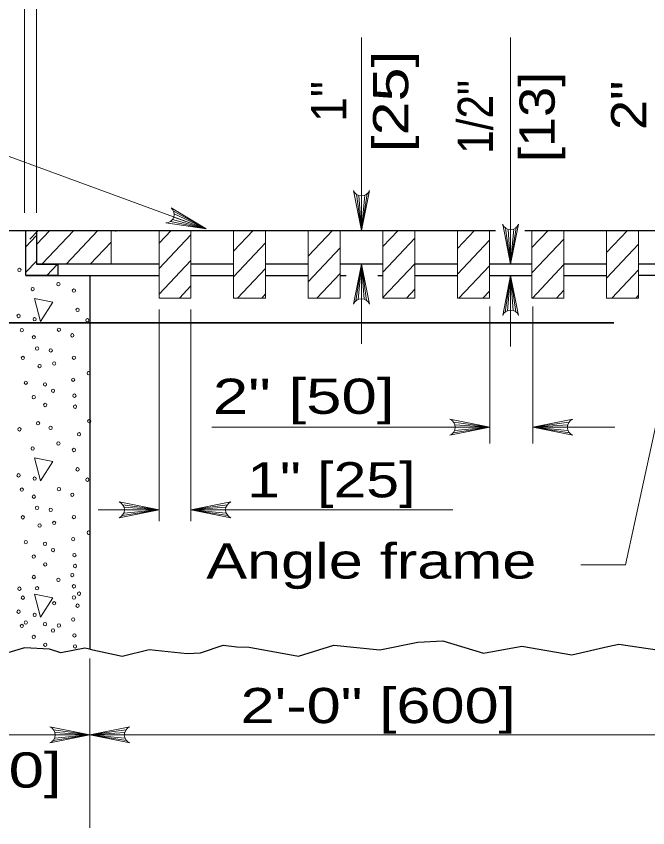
# Model space of a CAD drawing. Extents: x -410.5 to -376.5, y 1617.6 to 1661.6.
# Drawn here: x -394.159 to -391.362, y 1656.08 to 1659.678 of the extents above; entities that cross this region are included whole.
import ezdxf
from ezdxf.enums import TextEntityAlignment as Align

# ---------------------------------------------------------------- set-up
doc = ezdxf.new("R2010")
doc.units = 0
doc.header["$LTSCALE"] = 0.062
doc.layers.add('1', color=7, linetype='Continuous', lineweight=13)

msp = doc.modelspace()

# ---------------------------------------------------------------- linework, layer by layer
at = {"layer": '1'}
for p, q in [((-394.12283, 1658.80683), (-394.12283, 1659.937)), ((-394.06925, 1658.80683), (-394.06925, 1659.937)), ((-392.62967, 1658.72817), (-392.62967, 1659.58383)), ((-391.96883, 1658.57825), (-391.96883, 1659.58383)), ((-392.65208, 1658.88833), (-392.62967, 1658.72817)), ((-392.641, 1658.88292), (-392.62967, 1658.72817)), ((-392.60492, 1658.89025), (-392.62967, 1658.72817)), ((-392.61525, 1658.88417), (-392.62967, 1658.72817)), ((-392.62967, 1658.88133), (-392.62967, 1658.72817)), ((-393.46167, 1658.8135), (-393.31725, 1658.73575)), ((-393.46692, 1658.777), (-393.31725, 1658.73575)), ((-393.46158, 1658.78708), (-393.31725, 1658.73575)), ((-393.45942, 1658.80167), (-393.31725, 1658.73575)), ((-393.47575, 1658.76842), (-393.31725, 1658.73575)), ((-391.99125, 1658.7385), (-391.96883, 1658.57825)), ((-391.94408, 1658.74033), (-391.96883, 1658.57825)), ((-394.1165, 1658.65567), (-394.06933, 1658.70567)), ((-394.09842, 1658.68967), (-394.062, 1658.72817)), ((-394.06925, 1658.72817), (-394.06925, 1658.57825)), ((-394.06925, 1658.66575), (-394.01042, 1658.72808)), ((-394.04508, 1658.57833), (-393.90358, 1658.72808)), ((-393.93833, 1658.57833), (-393.79683, 1658.72808)), ((-393.73883, 1658.57825), (-393.73883, 1658.72817)), ((-393.71933, 1658.72375), (-393.71508, 1658.72817)), ((-393.5265, 1658.67183), (-393.47325, 1658.72817)), ((-393.5265, 1658.55875), (-393.38483, 1658.70867)), ((-393.34308, 1658.72817), (-393.48467, 1658.72817)), ((-393.19608, 1658.636), (-393.10908, 1658.72817)), ((-392.86567, 1658.61358), (-392.75758, 1658.72817)), ((-392.86567, 1658.72675), (-392.86433, 1658.72817)), ((-392.53533, 1658.65642), (-392.46758, 1658.72817)), ((-392.20483, 1658.64767), (-392.12883, 1658.72817)), ((-391.98017, 1658.733), (-391.96883, 1658.57825)), ((-391.9545, 1658.73425), (-391.96883, 1658.57825)), ((-391.96883, 1658.73142), (-391.96883, 1658.57825)), ((-391.8745, 1658.65258), (-391.80317, 1658.72817)), ((-391.54408, 1658.63008), (-391.45158, 1658.72817)), ((-393.8315, 1658.57833), (-393.73883, 1658.67642)), ((-393.19608, 1658.52292), (-393.0545, 1658.67283)), ((-392.53525, 1658.54342), (-392.39367, 1658.69333)), ((-392.20483, 1658.53458), (-392.06325, 1658.6845)), ((-391.8745, 1658.5395), (-391.73283, 1658.6895)), ((-391.54408, 1658.517), (-391.4025, 1658.667)), ((-392.86567, 1658.5005), (-392.72408, 1658.6505)), ((-394.1165, 1658.54267), (-394.06925, 1658.59258)), ((-393.5265, 1658.44567), (-393.38483, 1658.59558)), ((-394.02325, 1658.52825), (-393.97608, 1658.57825)), ((-393.17858, 1658.42833), (-393.0545, 1658.55983)), ((-392.65442, 1658.41608), (-392.62967, 1658.57825)), ((-392.64408, 1658.42225), (-392.62967, 1658.57825)), ((-392.62967, 1658.42508), (-392.62967, 1658.57825)), ((-392.61833, 1658.42342), (-392.62967, 1658.57825)), ((-392.60725, 1658.418), (-392.62967, 1658.57825)), ((-392.62967, 1658.57825), (-392.62967, 1658.22608)), ((-392.53525, 1658.43033), (-392.39367, 1658.58033)), ((-392.19842, 1658.42833), (-392.06325, 1658.5715)), ((-391.87275, 1658.42833), (-391.73283, 1658.57642)), ((-392.827, 1658.42833), (-392.72408, 1658.53742)), ((-391.99367, 1658.36608), (-391.96883, 1658.52825)), ((-391.98325, 1658.37225), (-391.96883, 1658.52825)), ((-391.96883, 1658.52825), (-391.96883, 1658.21383)), ((-391.96883, 1658.37508), (-391.96883, 1658.52825)), ((-391.9575, 1658.37342), (-391.96883, 1658.52825)), ((-391.94642, 1658.368), (-391.96883, 1658.52825)), ((-391.521, 1658.42833), (-391.4025, 1658.55392)), ((-393.436, 1658.42833), (-393.38483, 1658.4825)), ((-392.43042, 1658.42833), (-392.39367, 1658.46717)), ((-392.09158, 1658.42842), (-392.06325, 1658.45833)), ((-391.76592, 1658.42833), (-391.73283, 1658.46325)), ((-393.07175, 1658.42833), (-393.0545, 1658.44667)), ((-391.41425, 1658.42833), (-391.4025, 1658.44083)), ((-393.5265, 1658.37833), (-393.5265, 1657.43925)), ((-393.38483, 1658.37833), (-393.38483, 1657.43925)), ((-392.06133, 1658.39092), (-392.06133, 1657.78325)), ((-391.871, 1658.39092), (-391.871, 1657.78325)), ((-392.22158, 1657.87775), (-392.06133, 1657.85533)), ((-391.71075, 1657.87775), (-391.871, 1657.85533)), ((-393.29325, 1657.85533), (-392.0665, 1657.85533)), ((-392.2235, 1657.8305), (-392.06133, 1657.85533)), ((-392.21733, 1657.84092), (-392.06133, 1657.85533)), ((-392.21617, 1657.86658), (-392.06133, 1657.85533)), ((-392.2145, 1657.85533), (-392.06133, 1657.85533)), ((-391.71617, 1657.86658), (-391.871, 1657.85533)), ((-391.71783, 1657.85533), (-391.871, 1657.85533)), ((-391.715, 1657.84092), (-391.871, 1657.85533)), ((-391.70892, 1657.8305), (-391.871, 1657.85533)), ((-391.871, 1657.85533), (-391.50767, 1657.85533)), ((-393.79667, 1657.48925), (-393.5265, 1657.48925)), ((-393.68858, 1657.4645), (-393.5265, 1657.48925)), ((-393.68667, 1657.51167), (-393.5265, 1657.48925)), ((-393.6825, 1657.47483), (-393.5265, 1657.48925)), ((-393.68125, 1657.50058), (-393.5265, 1657.48925)), ((-393.67967, 1657.48925), (-393.5265, 1657.48925)), ((-393.22458, 1657.51167), (-393.38483, 1657.48925)), ((-393.23008, 1657.50058), (-393.38483, 1657.48925)), ((-393.23167, 1657.48925), (-393.38483, 1657.48925)), ((-393.22883, 1657.47483), (-393.38483, 1657.48925)), ((-393.22275, 1657.4645), (-393.38483, 1657.48925)), ((-393.38483, 1657.48925), (-392.22533, 1657.48925)), ((-393.83325, 1656.07967), (-393.83325, 1656.82983)), ((-393.9935, 1656.51367), (-393.83325, 1656.49125)), ((-393.673, 1656.51367), (-393.83325, 1656.49125)), ((-393.99542, 1656.4665), (-393.83325, 1656.49125)), ((-393.98925, 1656.47683), (-393.83325, 1656.49125)), ((-393.98808, 1656.50258), (-393.83325, 1656.49125)), ((-393.98642, 1656.49125), (-393.83325, 1656.49125)), ((-393.84033, 1656.49125), (-392.11067, 1656.49125)), ((-393.6785, 1656.50258), (-393.83325, 1656.49125)), ((-393.68008, 1656.49125), (-393.83325, 1656.49125)), ((-393.67725, 1656.47683), (-393.83325, 1656.49125)), ((-393.67117, 1656.4665), (-393.83325, 1656.49125)), ((-392.1675, 1656.49125), (-391.09567, 1656.49125))]:
    msp.add_line(p, q, dxfattribs=at)
at = {"layer": '1', "lineweight": 25}
for p, q in [((-394.14417, 1658.72817), (-394.09692, 1658.72817)), ((-394.1165, 1658.72817), (-392.03583, 1658.72817)), ((-391.90558, 1658.72817), (-390.8125, 1658.72817)), ((-393.527, 1658.57825), (-394.06925, 1658.57825)), ((-393.19542, 1658.57825), (-393.38483, 1658.57825)), ((-392.86633, 1658.57825), (-393.0545, 1658.57825)), ((-392.53475, 1658.57825), (-392.72408, 1658.57825)), ((-392.20567, 1658.57825), (-392.39483, 1658.57825)), ((-391.8745, 1658.57825), (-392.06325, 1658.57825)), ((-391.54408, 1658.57825), (-391.73283, 1658.57825)), ((-390.85967, 1658.57825), (-391.4025, 1658.57825)), ((-394.1165, 1658.52825), (-393.5265, 1658.52825)), ((-393.83325, 1658.52825), (-393.83325, 1656.87183)), ((-393.38483, 1658.52825), (-393.19608, 1658.52825)), ((-393.0545, 1658.52825), (-392.86567, 1658.52825)), ((-392.72408, 1658.52825), (-392.69817, 1658.52825)), ((-392.55742, 1658.52825), (-392.53642, 1658.52825)), ((-392.39483, 1658.52825), (-392.20483, 1658.52825)), ((-392.06325, 1658.52825), (-391.8745, 1658.52825)), ((-391.73283, 1658.52825), (-391.54408, 1658.52825)), ((-390.8125, 1658.52825), (-391.4025, 1658.52825))]:
    msp.add_line(p, q, dxfattribs=at)
at = {"layer": '1', "lineweight": 35}
for p, q in [((-395.32633, 1658.31867), (-393.57875, 1658.31867)), ((-393.57875, 1658.31867), (-391.51225, 1658.31867))]:
    msp.add_line(p, q, dxfattribs=at)
at = {"layer": '1'}
for points in [[(-393.31725, 1658.73575), (-394.90375, 1659.31708), (-395.14233, 1659.31708)], [(-392.59425, 1658.90517), (-392.62967, 1658.72817), (-392.66508, 1658.90517)], [(-393.47217, 1658.8285), (-393.31725, 1658.73575), (-393.49592, 1658.76175)], [(-391.9335, 1658.75525), (-391.96883, 1658.57825), (-392.00425, 1658.75525)], [(-393.19608, 1658.72817), (-393.19608, 1658.42833), (-393.0545, 1658.42833), (-393.0545, 1658.72817)], [(-392.66508, 1658.40125), (-392.62967, 1658.57825), (-392.59425, 1658.40125)], [(-392.00425, 1658.35125), (-391.96883, 1658.52825), (-391.9335, 1658.35125)], [(-391.18092, 1658.52825), (-391.4595, 1657.24567), (-391.65833, 1657.24567)], [(-392.23833, 1657.81992), (-392.06133, 1657.85533), (-392.23833, 1657.89067)], [(-391.694, 1657.81992), (-391.871, 1657.85533), (-391.694, 1657.89067)], [(-393.7035, 1657.45383), (-393.5265, 1657.48925), (-393.7035, 1657.52467)], [(-393.20783, 1657.45383), (-393.38483, 1657.48925), (-393.20783, 1657.52467)], [(-394.01025, 1656.45583), (-393.83325, 1656.49125), (-394.01025, 1656.52667)], [(-393.65625, 1656.45583), (-393.83325, 1656.49125), (-393.65625, 1656.52667)], [(-394.77725, 1656.49125), (-394.08308, 1656.49125), (-393.84033, 1656.49125)]]:
    msp.add_lwpolyline(points, dxfattribs=at)
at = {"layer": '1', "lineweight": 25}
for points in [[(-393.83325, 1656.87183), (-393.85467, 1656.87667), (-393.96075, 1656.85467), (-394.011, 1656.871), (-394.12183, 1656.87733), (-394.27542, 1656.83125), (-394.38142, 1656.86892), (-394.53508, 1656.83192), (-394.6515, 1656.87167), (-394.77725, 1656.87975), (-394.77725, 1658.5975), (-394.60742, 1658.72817), (-394.1165, 1658.72817)], [(-394.19133, 1658.72817), (-394.09692, 1658.72817), (-393.71933, 1658.72817)], [(-393.83325, 1656.87183), (-393.68983, 1656.83983), (-393.57033, 1656.87083), (-393.40175, 1656.85217), (-393.34308, 1656.855), (-393.2425, 1656.88925), (-393.18192, 1656.882), (-393.12783, 1656.87983), (-392.90825, 1656.84083), (-392.75167, 1656.88892), (-392.54808, 1656.86817), (-392.37933, 1656.90217), (-392.26933, 1656.909), (-392.08858, 1656.85375), (-391.91983, 1656.88475), (-391.69733, 1656.84675), (-391.53892, 1656.88275), (-391.48967, 1656.89375), (-391.23017, 1656.85558), (-391.09567, 1656.88817)]]:
    msp.add_lwpolyline(points, dxfattribs=at)
msp.add_lwpolyline([(-394.1165, 1658.52825), (-394.1165, 1658.72817), (-394.06925, 1658.72817), (-394.06925, 1658.57825), (-393.97483, 1658.57825), (-393.97483, 1658.52825)], close=True, dxfattribs=at)
at = {"layer": '1'}
for points in [[(-393.5265, 1658.72817), (-393.5265, 1658.42833), (-393.38483, 1658.42833), (-393.38483, 1658.72817)], [(-392.86567, 1658.72817), (-392.86567, 1658.42833), (-392.72408, 1658.42833), (-392.72408, 1658.72817)], [(-392.53525, 1658.72817), (-392.53525, 1658.42833), (-392.39367, 1658.42833), (-392.39367, 1658.72817)], [(-392.20483, 1658.72817), (-392.20483, 1658.42833), (-392.06325, 1658.42833), (-392.06325, 1658.72817)], [(-391.8745, 1658.72817), (-391.8745, 1658.42833), (-391.73283, 1658.42833), (-391.73283, 1658.72817)], [(-391.54408, 1658.72817), (-391.54408, 1658.42833), (-391.4025, 1658.42833), (-391.4025, 1658.72817)], [(-394.07833, 1658.42658), (-394.05133, 1658.32417), (-393.99633, 1658.41067)], [(-394.07833, 1657.71992), (-394.05133, 1657.61742), (-393.99633, 1657.70392)], [(-394.07833, 1657.11542), (-394.05133, 1657.01292), (-393.99633, 1657.09942)]]:
    msp.add_lwpolyline(points, close=True, dxfattribs=at)
for centre, start, end in [((-392.62971, 1658.91942), 202.08782, 337.91395), ((-393.49749, 1658.79989), 272.47392, 48.30005), ((-391.9689, 1658.76951), 202.08782, 337.91395), ((-392.62963, 1658.38692), 22.08782, 157.91395), ((-391.96882, 1658.33695), 22.08782, 157.91395), ((-392.25263, 1657.85533), 292.08605, 67.91218), ((-391.67972, 1657.85533), 112.08782, 247.91395), ((-393.71776, 1657.4893), 292.08605, 67.91218), ((-393.19357, 1657.4893), 112.08782, 247.91395), ((-394.02458, 1656.49131), 292.08605, 67.91218), ((-393.64199, 1656.49131), 112.08782, 247.91395)]:
    msp.add_arc(centre, 0.0382, start, end, dxfattribs=at)
for centre, major_axis in [((-394.14495, 1658.55313), (0, -0.00756)), ((-393.97196, 1658.49012), (0, 0.00756)), ((-394.08638, 1658.46815), (0, -0.00756)), ((-393.90342, 1658.46149), (0, 0.00756)), ((-393.88718, 1658.37563), (0, 0.00756)), ((-394.14851, 1658.34889), (0, 0.00756)), ((-394.07737, 1658.33458), (0, -0.00756)), ((-393.84391, 1658.32981), (0, 0.00756)), ((-394.1341, 1658.28594), (0, 0.00756)), ((-393.97012, 1658.28782), (0, -0.00756)), ((-393.91066, 1658.26303), (0, -0.00756)), ((-394.08098, 1658.25443), (0, 0.00756)), ((-394.06652, 1658.20484), (0, 0.00756)), ((-394.00617, 1658.19619), (0, -0.00756)), ((-394.12965, 1658.16285), (0, 0.00756)), ((-393.90342, 1658.16374), (0, -0.00756)), ((-394.05578, 1658.12658), (0, 0.00756)), ((-393.99087, 1658.13806), (0, -0.00756)), ((-393.83829, 1658.09478), (0, -0.00756)), ((-394.11642, 1658.05284), (0, 0.00756)), ((-394.03136, 1658.04548), (0, 0.00756)), ((-393.90671, 1658.06615), (0, -0.00756)), ((-393.99593, 1658.01751), (0, -0.00756)), ((-394.08126, 1657.98889), (0, 0.00756)), ((-393.90131, 1657.99554), (0, -0.00756)), ((-394.03047, 1657.9542), (0, -0.00756)), ((-393.89864, 1657.9469), (0, -0.00756)), ((-394.06201, 1657.87311), (0, -0.00756)), ((-393.83556, 1657.882), (0, 0.00756)), ((-394.14495, 1657.84643), (0, -0.00756)), ((-394.00706, 1657.85308), (0, -0.00756)), ((-393.8809, 1657.82446), (0, 0.00756)), ((-394.08638, 1657.76145), (0, -0.00756)), ((-393.97196, 1657.78342), (0, 0.00756)), ((-393.90342, 1657.75479), (0, 0.00756)), ((-393.88718, 1657.66893), (0, 0.00756)), ((-394.14851, 1657.64219), (0, 0.00756)), ((-394.07737, 1657.62788), (0, -0.00756)), ((-393.84391, 1657.62311), (0, 0.00756)), ((-394.1341, 1657.57924), (0, 0.00756)), ((-393.97012, 1657.58112), (0, -0.00756)), ((-394.08098, 1657.54773), (0, 0.00756)), ((-393.91066, 1657.55633), (0, -0.00756)), ((-394.06652, 1657.49814), (0, 0.00756)), ((-394.00617, 1657.48949), (0, -0.00756)), ((-394.12965, 1657.45615), (0, 0.00756)), ((-393.90342, 1657.45704), (0, -0.00756)), ((-394.05578, 1657.41988), (0, 0.00756)), ((-393.99087, 1657.43136), (0, -0.00756)), ((-393.83829, 1657.38808), (0, -0.00756)), ((-394.11642, 1657.34614), (0, 0.00756)), ((-394.03136, 1657.33878), (0, 0.00756)), ((-393.90671, 1657.35945), (0, -0.00756)), ((-393.99593, 1657.31081), (0, -0.00756)), ((-394.08126, 1657.28219), (0, 0.00756)), ((-393.90131, 1657.28884), (0, -0.00756)), ((-394.03047, 1657.2475), (0, -0.00756)), ((-393.89864, 1657.2402), (0, -0.00756)), ((-394.08098, 1657.19141), (0, 0.00756)), ((-393.91066, 1657.20001), (0, -0.00756)), ((-393.97196, 1657.17891), (0, 0.00756)), ((-393.90343, 1657.15029), (0, 0.00756)), ((-394.14495, 1657.13973), (0, -0.00756)), ((-394.06652, 1657.14182), (0, 0.00756)), ((-393.8809, 1657.11776), (0, 0.00756)), ((-394.12966, 1657.09983), (0, 0.00756)), ((-393.99087, 1657.07504), (0, -0.00756)), ((-393.90343, 1657.10072), (0, -0.00756)), ((-394.14851, 1657.03769), (0, 0.00756)), ((-393.88718, 1657.06443), (0, 0.00756)), ((-394.07737, 1657.02338), (0, -0.00756)), ((-393.90671, 1657.00313), (0, -0.00756)), ((-394.13411, 1656.97473), (0, 0.00756)), ((-394.11642, 1656.98982), (0, 0.00756)), ((-394.03137, 1656.98246), (0, 0.00756)), ((-393.97012, 1656.97662), (0, -0.00756)), ((-393.99593, 1656.95449), (0, -0.00756)), ((-393.90131, 1656.93252), (0, -0.00756)), ((-394.08126, 1656.92587), (0, 0.00756)), ((-394.03048, 1656.89118), (0, -0.00756)), ((-393.89864, 1656.88388), (0, -0.00756))]:
    msp.add_ellipse(centre, major_axis=major_axis, ratio=0.944543, dxfattribs=at)

# ---------------------------------------------------------------- texts
for s, width, p in [('[25]', 1.3, (-392.42258, 1659.29987)), ('1/2"', 0.9, (-392.04775, 1659.23142)), ('[13]', 1.15, (-391.77375, 1659.23142)), ('1"', 0.95, (-392.69658, 1659.29987)), ('2"', 1.15, (-391.36792, 1659.28271))]:
    msp.add_text(s, height=0.156, rotation=90, dxfattribs=dict(at, width=width)).set_placement(p, align=Align.CENTER)
for s, width, p in [('2" [50]', 1.35, (-393.288, 1657.915)), ('1" [25]', 1.25, (-393.13575, 1657.54467)), ('Angle frame', 1.3, (-393.31733, 1657.18458)), ('2\'-0" [600]', 1.3, (-393.16533, 1656.54358))]:
    msp.add_text(s, height=0.156, dxfattribs=dict(at, width=width)).set_placement(p)
at = {"layer": '1', "width": 1.35}
msp.add_text('[200]', height=0.156, dxfattribs=at).set_placement((-394.27108, 1656.25775), align=Align.CENTER)

doc.saveas('drawing.dxf')
